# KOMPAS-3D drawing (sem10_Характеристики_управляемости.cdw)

Views: Вид 1
Referenced files: dinhar1.cdw
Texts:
  Автопилот стабилизации угла крена
  Управляемость
  Hornet
  Normal
  Microsoft Sans Serif
  Анализ управляемости ЛА
  Математический критерий допустимости анализа ЛА как объекта управления в боковом
  движении на основании анализа изолированных движений рыскание-скольжение и крена:
  Результаты проверки критерия:
  № режима
  результат
  Оптимизация структуры АП
  На тех режимах, где   <1,75рад/c, необходим АБУ, то есть на режимах 4, 9, 12
  Параметры автомата бокового управления:
  Область оценки управляемости ЛА по крену
  Показатели управляемости ЛА по углам рыскание-скольжение
  по углу скольжения
  по углу скольжения при нулевом крене
  Область оценки показателей управляемости изолированного
  движения рыскание-скольжение:
  приемлемо
  удовлетворительно
  допустимо
  неудовл.
  удовл.
  Пашинин С.А.
  Окоемов Б.Н.
  МГТУ им. Н. Э. Баумана
  Кафедра ИУ2
  Группа ИУ2-102
  Автопилот крена-
Dimensions and other numbers on the sheet: 1; 2; 3; 4; 5; 6; 7; 8; 9; 10; 11; 12; 1,03; 1,04; 1,05; 0,94; 1,06; 1,07; 0,95; 1,09; 1,01; 0,6; 2,06; 0,36; 0,16; 3,31; 2,45; 0,59; 0,08; 3,21; 18; 3,96; 0,96; 0,06; 3,00; 2,38; 0,19; 5,12; 0,18; 7,52; 0,22; 1,67; 0,15; 6,4; 0,17; 2,54; 0,11; 4,27; 0,14; 4,69; 0,13; 1,66; 2,82; 0,09; 3,2; 0,1; 1,42; 0,07; 0,90; 5,64; 1,91; 26,23; 3,40; 56,66; 0,51; 2,80; 2,26; 41,02; 0,56; 6,47; 1,17; 18,27; 1,27; 22,04; 0,26; 2,78; 0,54; 0,69; 0,21; 7,98; 10,09; 2,04; 0,5; 50; 0; 0,2; 0,4; 0,8; 1,0; 1,2; 1:1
